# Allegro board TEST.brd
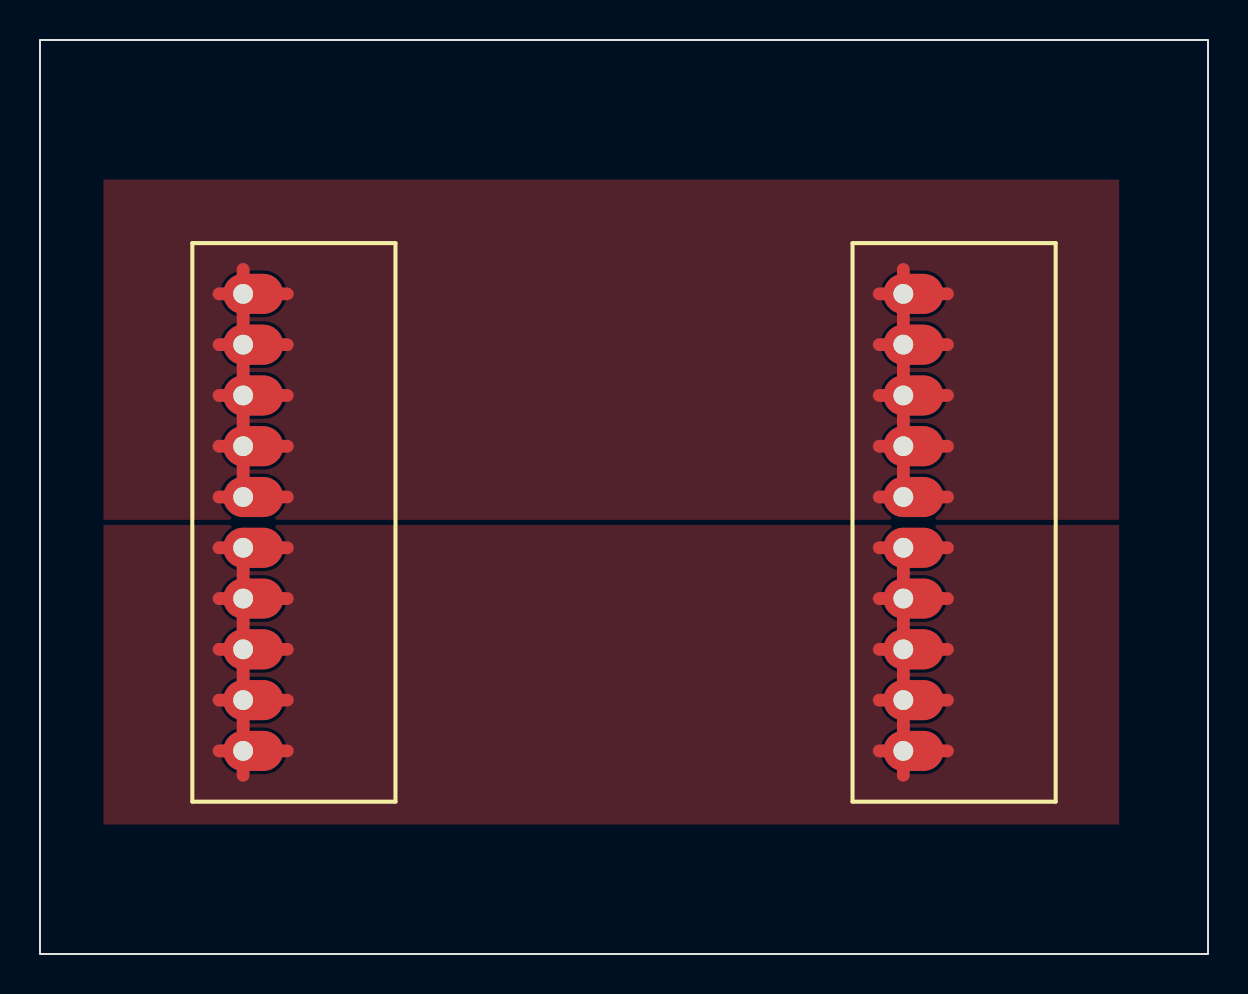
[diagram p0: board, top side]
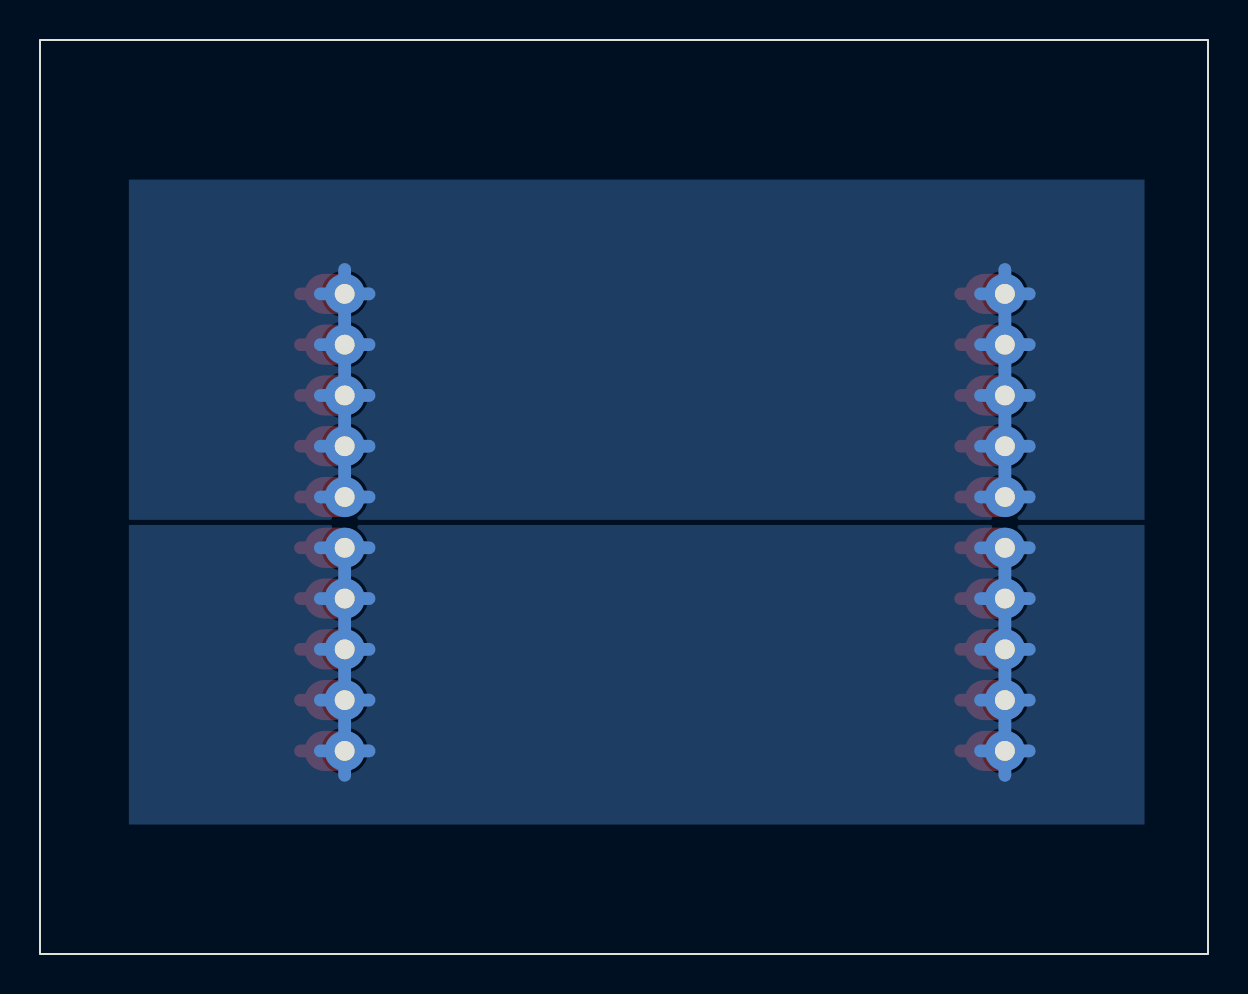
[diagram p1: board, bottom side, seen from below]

Outline 58.42 x 45.72 mm; copper layers: TOP, GND, VCC, BOTTOM. Coordinates in mm from the lower left corner of the outline.
Outline path: rectangle 0,0 58.42,45.72

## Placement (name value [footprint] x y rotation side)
J1  HEADER 10/SM  [CONNECTOR_OFFSET]  10.16 33.02 270 top
J2  HEADER 10/SM  [CONNECTOR_OFFSET]  43.18 33.02 270 top

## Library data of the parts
J1 J2 = HEADER 10/SM

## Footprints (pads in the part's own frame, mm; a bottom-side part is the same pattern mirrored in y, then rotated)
CONNECTOR_OFFSET
  oval 2.007x2.997 hole 0.991: 1(0,0) 2(2.54,0) 3(5.08,0) 4(7.62,0) 5(10.16,0) 6(12.7,0) 7(15.24,0) 8(17.78,0) 9(20.32,0) 10(22.86,0)

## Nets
GND: J1.1 J1.2 J1.3 J1.4 J1.5 J2.1 J2.2 J2.3 J2.4 J2.5
VCC: J1.6 J1.7 J1.8 J1.9 J1.10 J2.6 J2.7 J2.8 J2.9 J2.10

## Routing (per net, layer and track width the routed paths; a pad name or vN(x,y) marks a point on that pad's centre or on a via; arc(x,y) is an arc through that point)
GND: length 195
  TOP w0.635: J1.2 12.37,30.48 ; J1.2 8.97,30.48 ; J1.2 10.16,29.26 ; J1.2 10.16,31.7 ; J1.1 12.37,33.02 ; J1.1 8.97,33.02 ; J1.1 10.16,34.24 ; J1.1 10.16,31.8 ; J2.3 43.18,29.16 ; J2.3 41.99,27.94 ; J2.3 43.18,26.72 ; J2.3 45.39,27.94 ; J1.4 12.37,25.4 ; J1.4 10.16,24.18 ; J1.4 10.16,26.62 ; J1.4 8.97,25.4 ; J1.5 10.16,24.08 ; J1.5 8.97,22.86 ; J1.5 12.37,22.86 ; J2.1 43.18,34.24 ; J2.1 45.39,33.02 ; J2.1 41.99,33.02 ; J2.1 43.18,31.8 ; J2.5 45.39,22.86 ; J2.5 41.99,22.86 ; J2.5 43.18,24.08 ; 43.18,24.18 J2.4 ; J2.4 43.18,26.62 ; J2.4 41.99,25.4 ; J2.4 45.39,25.4 ; 8.97,27.94 J1.3 ; J1.3 10.16,29.16 ; J1.3 10.16,26.72 ; J1.3 12.37,27.94 ; J2.2 45.39,30.48 ; J2.2 43.18,29.26 ; J2.2 41.99,30.48 ; J2.2 43.18,31.7
  GND w0.635: 41.96,30.48 J2.2 ; J2.2 43.18,29.26 ; J2.2 44.4,30.48 ; J2.2 43.18,31.7 ; 41.96,22.86 J2.5 ; J2.5 43.18,24.08 ; J2.5 44.4,22.86 ; J1.1 10.16,34.24 ; J1.1 10.16,31.8 ; J1.1 11.38,33.02 ; J1.1 8.94,33.02 ; 10.16,24.18 J1.4 ; J1.4 10.16,26.62 ; J1.4 8.94,25.4 ; J1.4 11.38,25.4 ; J1.3 10.16,29.16 ; J1.3 8.94,27.94 ; J1.3 10.16,26.72 ; J1.3 11.38,27.94 ; 41.96,25.4 J2.4 ; J2.4 43.18,26.62 ; J2.4 43.18,24.18 ; J2.4 44.4,25.4 ; 43.18,26.72 J2.3 ; J2.3 44.4,27.94 ; J2.3 43.18,29.16 ; J2.3 41.96,27.94 ; 41.96,33.02 J2.1 ; J2.1 43.18,31.8 ; J2.1 44.4,33.02 ; J2.1 43.18,34.24 ; 8.94,22.86 J1.5 ; J1.5 11.38,22.86 ; J1.5 10.16,24.08 ; J1.2 11.38,30.48 ; J1.2 8.94,30.48 ; J1.2 10.16,31.7 ; J1.2 10.16,29.26
  VCC w0.635: J1.2 10.16,31.7 ; J1.2 11.38,30.48 ; J1.2 10.16,29.26 ; J1.2 8.94,30.48 ; J1.3 11.38,27.94 ; J1.3 10.16,29.16 ; J1.3 8.94,27.94 ; J1.3 10.16,26.72 ; 10.16,31.8 J1.1 ; J1.1 8.94,33.02 ; J1.1 10.16,34.24 ; J1.1 11.38,33.02 ; J2.3 43.18,29.16 ; J2.3 41.96,27.94 ; J2.3 43.18,26.72 ; J2.3 44.4,27.94 ; 10.16,24.18 J1.4 ; J1.4 8.94,25.4 ; J1.4 10.16,26.62 ; J1.4 11.38,25.4 ; 8.94,22.86 J1.5 ; J1.5 10.16,24.08 ; J1.5 11.38,22.86 ; J2.4 43.18,26.62 ; J2.4 41.96,25.4 ; J2.4 44.4,25.4 ; J2.4 43.18,24.18 ; J2.5 44.4,22.86 ; J2.5 41.96,22.86 ; J2.5 43.18,24.08 ; 43.18,31.8 J2.1 ; J2.1 41.96,33.02 ; J2.1 44.4,33.02 ; J2.1 43.18,34.24 ; J2.2 44.4,30.48 ; J2.2 41.96,30.48 ; J2.2 43.18,31.7 ; J2.2 43.18,29.26
  BOTTOM w0.635: J1.1 10.16,34.24 ; J1.1 10.16,31.8 ; J1.1 11.38,33.02 ; J1.1 8.94,33.02 ; 41.96,30.48 J2.2 ; J2.2 43.18,31.7 ; J2.2 44.4,30.48 ; J2.2 43.18,29.26 ; 43.18,31.8 J2.1 ; J2.1 41.96,33.02 ; J2.1 43.18,34.24 ; J2.1 44.4,33.02 ; 43.18,26.72 J2.3 ; J2.3 44.4,27.94 ; J2.3 41.96,27.94 ; J2.3 43.18,29.16 ; 10.16,24.18 J1.4 ; J1.4 10.16,26.62 ; J1.4 11.38,25.4 ; J1.4 8.94,25.4 ; J1.5 10.16,24.08 ; J1.5 8.94,22.86 ; J1.5 11.38,22.86 ; J2.5 44.4,22.86 ; J2.5 41.96,22.86 ; J2.5 43.18,24.08 ; J1.2 10.16,31.7 ; J1.2 10.16,29.26 ; J1.2 8.94,30.48 ; J1.2 11.38,30.48 ; J2.4 44.4,25.4 ; J2.4 43.18,26.62 ; J2.4 41.96,25.4 ; J2.4 43.18,24.18 ; J1.3 10.16,29.16 ; J1.3 10.16,26.72 ; J1.3 8.94,27.94 ; J1.3 11.38,27.94
VCC: length 195
  TOP w0.635: J2.6 45.39,20.32 ; J2.6 41.99,20.32 ; J2.6 43.18,19.1 ; J1.10 12.37,10.16 ; J1.10 8.97,10.16 ; J1.10 10.16,11.38 ; J1.10 10.16,8.94 ; J1.8 12.37,15.24 ; J1.8 8.97,15.24 ; J1.8 10.16,16.46 ; J1.8 10.16,14.02 ; 43.18,8.94 J2.10 ; J2.10 43.18,11.38 ; J2.10 45.39,10.16 ; J2.10 41.99,10.16 ; 41.99,15.24 J2.8 ; J2.8 43.18,14.02 ; J2.8 45.39,15.24 ; J2.8 43.18,16.46 ; J2.7 45.39,17.78 ; J2.7 43.18,19 ; J2.7 43.18,16.56 ; J2.7 41.99,17.78 ; 41.99,12.7 J2.9 ; J2.9 43.18,11.48 ; J2.9 45.39,12.7 ; J2.9 43.18,13.92 ; 10.16,16.56 J1.7 ; J1.7 8.97,17.78 ; J1.7 10.16,19 ; J1.7 12.37,17.78 ; 8.97,12.7 J1.9 ; J1.9 10.16,11.48 ; J1.9 10.16,13.92 ; J1.9 12.37,12.7 ; 8.97,20.32 J1.6 ; J1.6 10.16,19.1 ; J1.6 12.37,20.32
  GND w0.635: 10.16,14.02 J1.8 ; J1.8 11.38,15.24 ; J1.8 8.94,15.24 ; J1.8 10.16,16.46 ; 43.18,11.48 J2.9 ; J2.9 43.18,13.92 ; J2.9 41.96,12.7 ; J2.9 44.4,12.7 ; 43.18,14.02 J2.8 ; J2.8 44.4,15.24 ; J2.8 41.96,15.24 ; J2.8 43.18,16.46 ; J1.9 11.38,12.7 ; J1.9 8.94,12.7 ; J1.9 10.16,11.48 ; J1.9 10.16,13.92 ; J2.6 44.4,20.32 ; J2.6 43.18,19.1 ; J2.6 41.96,20.32 ; 8.94,17.78 J1.7 ; J1.7 10.16,16.56 ; J1.7 11.38,17.78 ; J1.7 10.16,19 ; 8.94,10.16 J1.10 ; J1.10 10.16,8.94 ; J1.10 10.16,11.38 ; J1.10 11.38,10.16 ; 41.96,17.78 J2.7 ; J2.7 44.4,17.78 ; J2.7 43.18,19 ; J2.7 43.18,16.56 ; 43.18,8.94 J2.10 ; J2.10 43.18,11.38 ; J2.10 41.96,10.16 ; J2.10 44.4,10.16 ; J1.6 11.38,20.32 ; J1.6 10.16,19.1 ; J1.6 8.94,20.32
  VCC w0.635: 41.96,15.24 J2.8 ; J2.8 43.18,16.46 ; J2.8 43.18,14.02 ; J2.8 44.4,15.24 ; J2.9 44.4,12.7 ; J2.9 43.18,11.48 ; J2.9 41.96,12.7 ; J2.9 43.18,13.92 ; 8.94,20.32 J1.6 ; J1.6 11.38,20.32 ; J1.6 10.16,19.1 ; J2.6 44.4,20.32 ; J2.6 41.96,20.32 ; J2.6 43.18,19.1 ; J1.9 11.38,12.7 ; J1.9 8.94,12.7 ; J1.9 10.16,13.92 ; J1.9 10.16,11.48 ; 41.96,10.16 J2.10 ; J2.10 43.18,11.38 ; J2.10 44.4,10.16 ; J2.10 43.18,8.94 ; 10.16,14.02 J1.8 ; J1.8 8.94,15.24 ; J1.8 10.16,16.46 ; J1.8 11.38,15.24 ; 8.94,17.78 J1.7 ; J1.7 10.16,19 ; J1.7 11.38,17.78 ; J1.7 10.16,16.56 ; J2.7 44.4,17.78 ; J2.7 43.18,19 ; J2.7 43.18,16.56 ; J2.7 41.96,17.78 ; 10.16,8.94 J1.10 ; J1.10 8.94,10.16 ; J1.10 11.38,10.16 ; J1.10 10.16,11.38
  BOTTOM w0.635: J2.10 43.18,11.38 ; J2.10 41.96,10.16 ; J2.10 44.4,10.16 ; J2.10 43.18,8.94 ; 43.18,19.1 J2.6 ; J2.6 44.4,20.32 ; J2.6 41.96,20.32 ; 10.16,16.56 J1.7 ; J1.7 10.16,19 ; J1.7 8.94,17.78 ; J1.7 11.38,17.78 ; J2.9 43.18,13.92 ; J2.9 43.18,11.48 ; J2.9 41.96,12.7 ; J2.9 44.4,12.7 ; J1.10 11.38,10.16 ; J1.10 10.16,8.94 ; J1.10 8.94,10.16 ; J1.10 10.16,11.38 ; 8.94,12.7 J1.9 ; J1.9 11.38,12.7 ; J1.9 10.16,11.48 ; J1.9 10.16,13.92 ; J2.8 43.18,16.46 ; J2.8 41.96,15.24 ; J2.8 43.18,14.02 ; J2.8 44.4,15.24 ; 8.94,15.24 J1.8 ; J1.8 10.16,14.02 ; J1.8 11.38,15.24 ; J1.8 10.16,16.46 ; 41.96,17.78 J2.7 ; J2.7 44.4,17.78 ; J2.7 43.18,16.56 ; J2.7 43.18,19 ; 10.16,19.1 J1.6 ; J1.6 8.94,20.32 ; J1.6 11.38,20.32

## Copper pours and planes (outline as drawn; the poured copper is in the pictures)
GND on TOP, BOTTOM, GND, VCC: 3.18,38.73 3.18,21.72 53.98,21.72 53.98,38.73
VCC on TOP, BOTTOM, GND, VCC: 3.18,21.46 3.18,6.48 53.98,6.48 53.98,21.46
